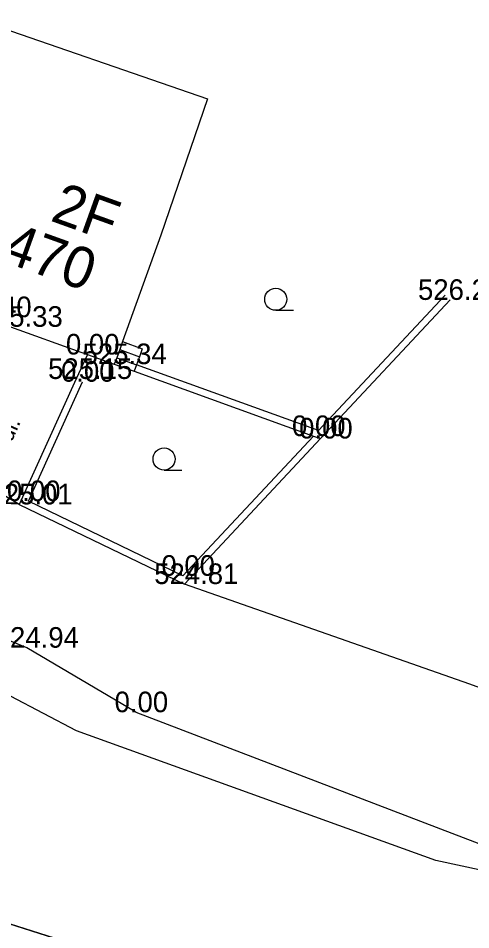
# Model space of a CAD drawing. Extents: x -669393 to -668650, y -1126925 to -1126294.
# Drawn here: x -668903.24 to -668886.74, y -1126829.82 to -1126796.62 of the extents above; entities that cross this region are included whole.
import ezdxf

# ---------------------------------------------------------------- set-up
doc = ezdxf.new("R2010")
doc.units = 0
for name, color, linetype in [('G_Bod_tecka', 7, 'Continuous'), ('G_Bod_vyska', 7, 'Continuous'), ('G_Budovy_Objekty', 7, 'Continuous'), ('G_Budovy_vstupy', 7, 'Continuous'), ('G_Cesty_Schody', 7, 'Continuous'), ('G_Cisla_orientacni', 7, 'Continuous'), ('G_Cisla_popisna', 7, 'Continuous'), ('G_Plochy_zpevnene', 7, 'Continuous'), ('G_Ploty', 7, 'Continuous'), ('G_Ploty_vstupy', 7, 'Continuous'), ('G_Popisy_povrchu', 7, 'Continuous'), ('G_Z_KANAL_podz_priblizne', 7, 'Continuous'), ('G_Z_SPOJE_podz_kotovane', 7, 'Continuous'), ('G_Zelen-Znacky', 7, 'Continuous'), ('Vrstva 18', 7, 'Continuous')]:
    doc.layers.add(name, color=color, linetype=linetype)

msp = doc.modelspace()

# ---------------------------------------------------------------- linework, layer by layer
at = {"layer": 'G_Bod_tecka'}
for p, q in [((-668887.49, -1126806.88), (-668887.49, -1126806.88)), ((-668900.72, -1126808.87), (-668900.72, -1126808.87)), ((-668899.74, -1126809.22), (-668899.74, -1126809.22)), ((-668901.13, -1126809.76), (-668901.13, -1126809.76)), ((-668900.9, -1126809.86), (-668900.9, -1126809.86)), ((-668892.48, -1126811.84), (-668892.48, -1126811.84)), ((-668892.22, -1126811.93), (-668892.22, -1126811.93)), ((-668903.2, -1126814.33), (-668903.2, -1126814.33)), ((-668902.87, -1126814.21), (-668902.87, -1126814.21)), ((-668897.24, -1126816.93), (-668897.24, -1126816.93)), ((-668897.18, -1126817.23), (-668897.18, -1126817.23)), ((-668902.93, -1126819.55), (-668902.93, -1126819.55)), ((-668898.95, -1126821.9), (-668898.95, -1126821.9))]:
    msp.add_line(p, q, dxfattribs=at)
at = {"layer": 'G_Budovy_Objekty'}
for p, q in [((-668898.04, -1126804.52), (-668899.44, -1126808.4)), ((-668899.44, -1126808.4), (-668899.54, -1126808.69)), ((-668899.54, -1126808.69), (-668899.65, -1126808.99)), ((-668899.65, -1126808.99), (-668899.74, -1126809.22))]:
    msp.add_line(p, q, dxfattribs=at)
for points in [[(-668904.87, -1126796.62), (-668896.34, -1126799.56)], [(-668896.34, -1126799.56), (-668898.04, -1126804.52)], [(-668900.96, -1126808.78), (-668900.72, -1126808.87), (-668899.74, -1126809.22)]]:
    msp.add_lwpolyline(points, dxfattribs=at)
at = {"layer": 'G_Budovy_vstupy'}
msp.add_line((-668903.52, -1126807.86), (-668900.96, -1126808.78), dxfattribs=at)
at = {"layer": 'G_Cesty_Schody'}
for p, q in [((-668899.44, -1126808.4), (-668898.72, -1126808.66)), ((-668899.54, -1126808.69), (-668898.82, -1126808.95)), ((-668898.72, -1126808.66), (-668898.82, -1126808.95)), ((-668899.65, -1126808.99), (-668898.93, -1126809.25)), ((-668898.82, -1126808.95), (-668898.93, -1126809.25)), ((-668899.74, -1126809.22), (-668899.01, -1126809.48)), ((-668898.93, -1126809.25), (-668899.01, -1126809.48))]:
    msp.add_line(p, q, dxfattribs=at)
at = {"layer": 'G_Plochy_zpevnene'}
msp.add_line((-668903.2, -1126814.33), (-668905.8, -1126812.82), dxfattribs=at)
for points in [[(-668902.93, -1126819.55), (-668911.95, -1126815.83)], [(-668794.8, -1126825.6), (-668795.84, -1126825.39), (-668796.83, -1126825.24), (-668798.69, -1126825.06), (-668800.34, -1126825.01), (-668801.78, -1126825.02), (-668811.94, -1126825.73), (-668821.93, -1126826.15), (-668831.92, -1126826.62), (-668839.86, -1126827.06), (-668847.81, -1126827.52), (-668851.35, -1126827.68), (-668854.02, -1126827.75), (-668858.01, -1126827.77), (-668862, -1126827.68), (-668863.7, -1126827.58), (-668865.18, -1126827.44), (-668867.77, -1126827.06), (-668869.7, -1126826.68), (-668871.12, -1126826.34), (-668873.25, -1126825.74), (-668875.33, -1126825.04), (-668886.78, -1126820.88), (-668897.18, -1126817.23)], [(-668898.95, -1126821.9), (-668902.93, -1126819.55)], [(-668898.95, -1126821.9), (-668887.43, -1126826.31), (-668875.91, -1126830.71), (-668875.01, -1126831.01), (-668874.15, -1126831.24), (-668872.51, -1126831.53), (-668871.04, -1126831.69), (-668865.85, -1126831.96), (-668864.56, -1126832.08), (-668863.6, -1126832.21), (-668862.2, -1126832.5), (-668860.82, -1126832.92), (-668858.11, -1126834.02), (-668855.45, -1126835.23), (-668851.15, -1126837.23), (-668849.02, -1126838.26), (-668846.94, -1126839.39), (-668832.81, -1126847.59), (-668818.68, -1126855.79)]]:
    msp.add_lwpolyline(points, dxfattribs=at)
at = {"layer": 'G_Ploty'}
for p, q in [((-668887.68, -1126806.71), (-668892.29, -1126811.64)), ((-668887.49, -1126806.88), (-668892.22, -1126811.93)), ((-668892.29, -1126811.64), (-668898.93, -1126809.25)), ((-668901.13, -1126809.76), (-668903.2, -1126814.33)), ((-668902.87, -1126814.21), (-668900.9, -1126809.86)), ((-668892.48, -1126811.84), (-668897.24, -1126816.93)), ((-668897.24, -1126816.93), (-668902.87, -1126814.21))]:
    msp.add_line(p, q, dxfattribs=at)
for points in [[(-668899.01, -1126809.48), (-668892.48, -1126811.84), (-668892.22, -1126811.93)], [(-668903.2, -1126814.33), (-668897.18, -1126817.23), (-668892.22, -1126811.93)]]:
    msp.add_lwpolyline(points, dxfattribs=at)
at = {"layer": 'G_Ploty_vstupy'}
msp.add_line((-668900.72, -1126808.87), (-668901.13, -1126809.76), dxfattribs=at)
at = {"layer": 'G_Z_KANAL_podz_priblizne'}
msp.add_lwpolyline([(-668952.37, -1126814.08), (-668872.81, -1126839.39), (-668858.24, -1126860.51)], dxfattribs=at)
at = {"layer": 'G_Z_SPOJE_podz_kotovane'}
msp.add_lwpolyline([(-668874.36, -1126831.78), (-668883.8, -1126828.77), (-668885.48, -1126827.85), (-668888.02, -1126827.3), (-668901.12, -1126822.58), (-668907.14, -1126819.42), (-668924.36, -1126812.03), (-668938.42, -1126806.85)], dxfattribs=at)
at = {"layer": 'G_Zelen-Znacky'}
for p, q in [((-668893.852, -1126807.26), (-668893.202, -1126807.257)), ((-668897.922, -1126813.08), (-668897.272, -1126813.077))]:
    msp.add_line(p, q, dxfattribs=at)
for centre in [(-668893.852, -1126806.857), (-668897.922, -1126812.677)]:
    msp.add_circle(centre, 0.403, dxfattribs=at)
at = {"layer": 'Vrstva 18'}
msp.add_lwpolyline([(-668952.37, -1126814.08), (-668872.812, -1126839.386), (-668858.241, -1126860.513)], dxfattribs=at)
msp.add_lwpolyline([(-668952.37, -1126814.08), (-668872.812, -1126839.386), (-668858.241, -1126860.513)], dxfattribs=at)

# ---------------------------------------------------------------- texts
at = {"layer": 'G_Bod_vyska'}
for s, p in [('526.27', (-668888.668, -1126806.88)), ('526.40', (-668905.819, -1126807.51)), ('525.33', (-668904.684, -1126807.86)), ('0.00', (-668901.5, -1126808.87)), ('525.34', (-668900.894, -1126809.22)), ('525.15', (-668902.152, -1126809.76)), ('0.00', (-668901.68, -1126809.86)), ('0.00', (-668893.26, -1126811.84)), ('0.00', (-668893, -1126811.93)), ('525.01', (-668904.324, -1126814.33)), ('0.00', (-668903.65, -1126814.21)), ('0.00', (-668898.02, -1126816.93)), ('524.81', (-668898.282, -1126817.23)), ('524.94', (-668904.096, -1126819.55)), ('0.00', (-668899.727, -1126821.9))]:
    msp.add_text(s, height=0.75, dxfattribs=at).set_placement(p)
at = {"layer": 'G_Cisla_orientacni'}
msp.add_text('2F', height=1.5, rotation=340.2164, dxfattribs=at).set_placement((-668902.112, -1126803.982))
at = {"layer": 'G_Cisla_popisna'}
msp.add_text('4470', height=1.5, rotation=340.2164, dxfattribs=at).set_placement((-668904.955, -1126805.067))
at = {"layer": 'G_Popisy_povrchu'}
msp.add_text('z.dl.', height=0.6, rotation=65.6317, dxfattribs=at).set_placement((-668903.743, -1126812.657))

doc.saveas('drawing.dxf')
